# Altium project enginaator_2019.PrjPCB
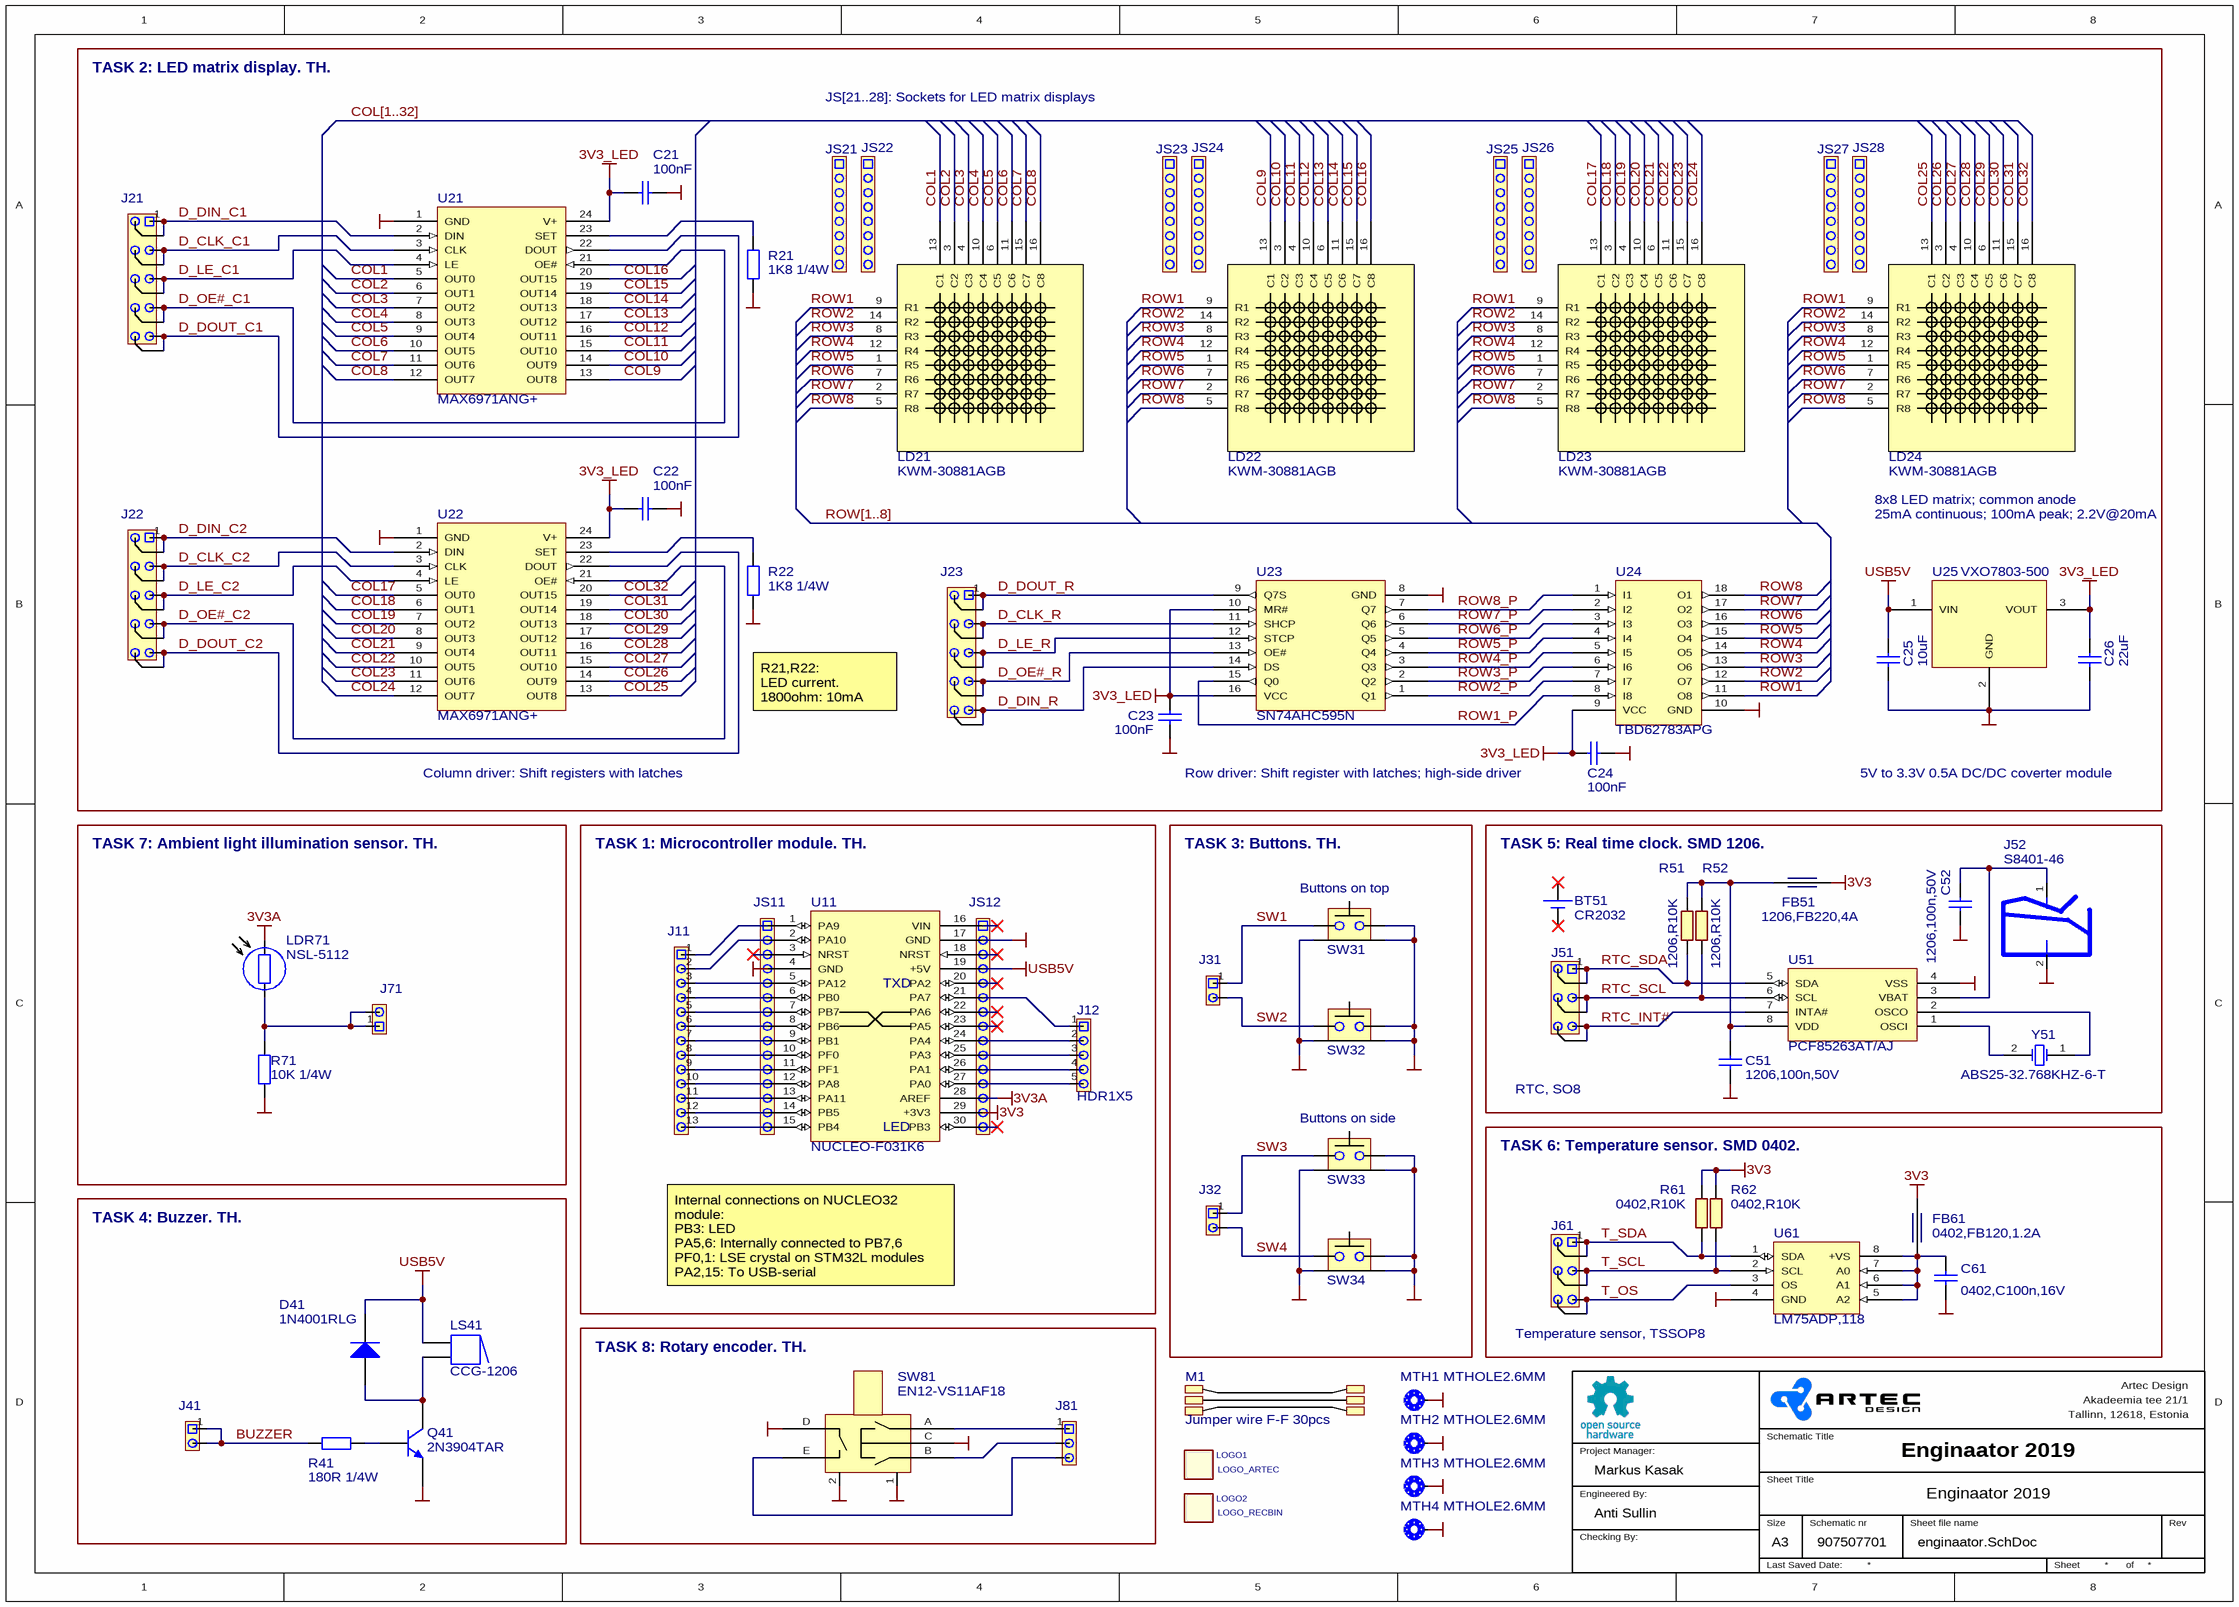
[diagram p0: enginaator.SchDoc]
ClientNr: 75; PCBDesigner: Anti Sullin; ProjectManager: Markus Kasak; ProjectNr: 077; ProjectTitle: Enginaator 2019; SchDesigner: Anti Sullin; Schematic_Title: Enginaator 2019; VersionNr: 01
1 sheet, 72 parts. Net scope: global (net labels, ports and power ports of the same name join across sheets).
Board file: enginaator.PcbDoc

## Sheet enginaator.SchDoc: Enginaator 2019
size A3; Size: A3

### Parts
BT51  CR2032  (mechanical)
C21  100nF  [CAP_TH_RADIAL_5MM]
C22  100nF  [CAP_TH_RADIAL_5MM]
C23  100nF  [CAP_TH_RADIAL_5MM]
C24  100nF  [CAP_TH_RADIAL_5MM]
C25  10uF  [CAP_TH_RADIAL_5MM]
C26  22uF  [CAP_TH_RADIAL_5MM]
C51  1206,100n,50V  [C1206]
C52  1206,100n,50V  [C1206]
C61  0402,C100n,16V  [C0402]
D41  1N4001RLG  [DIODE_TH_4x2MM]
FB51  1206,FB220,4A  [L1206]
FB61  0402,FB120,1.2A  [L0402]
J11  HDR1X13  [HDRTHV254P_1X13]  (value not drawn)
J12  HDR1X5  [HDRTHV254P_1X5]
J21  HDR2X5  [HDRTHv254P_2X5]  (value not drawn)
J22  HDR2X5  [hdrthv254p_2x5]  (value not drawn)
J23  HDR2X5  [hdrthv254p_2x5]  (value not drawn)
J31  HDR1X2  [HDRTHV254P_1X2]  (value not drawn)
J32  HDR1X2  [HDRTHV254P_1X2]  (value not drawn)
J41  HDR1X2  [HDRTHV254P_1X2]  (value not drawn)
J51  HDR2X3  [HDRTHV254P_2X3]  (value not drawn)
J52  S8401-46  [S8401-46]
J61  HDR2X3  [HDRTHV254P_2X3]  (value not drawn)
J71  HDR1X2  [HDRTHV254P_1X2]  (value not drawn)
J81  HDR1X3  [HDRTHV254P_1X3]  (value not drawn)
JS11  SOCKET_1X15  [HDRTHV254P_1X15_MECH]  (value not drawn)
JS12  SOCKET_1X15  [HDRTHV254P_1X15_MECH]  (value not drawn)
JS21  SOCKET_1X8  [HDRTHV254P_1X8_MECH]  (value not drawn)
JS22  SOCKET_1X8  [HDRTHV254P_1X8_MECH]  (value not drawn)
JS23  SOCKET_1X8  [HDRTHV254P_1X8_MECH]  (value not drawn)
JS24  SOCKET_1X8  [HDRTHV254P_1X8_MECH]  (value not drawn)
JS25  SOCKET_1X8  [HDRTHV254P_1X8_MECH]  (value not drawn)
JS26  SOCKET_1X8  [HDRTHV254P_1X8_MECH]  (value not drawn)
JS27  SOCKET_1X8  [HDRTHV254P_1X8_MECH]  (value not drawn)
JS28  SOCKET_1X8  [HDRTHV254P_1X8_MECH]  (value not drawn)
LD21  KWM-30881AGB  [LED8x8_32x32mm]
LD22  KWM-30881AGB  [LED8x8_32x32mm]
LD23  KWM-30881AGB  [LED8x8_32x32mm]
LD24  KWM-30881AGB  [LED8x8_32x32mm]
LDR71  NSL-5112  [PHOTODIODE_4MM]
LOGO1  LOGO_ARTEC  [LOGO_ARTEC]  (no BOM)
LOGO2  LOGO_RECBIN  [LOGO_RECBIN]  (no BOM)
LS41  CCG-1206  [BUZZER_12MM]
M1  Jumper wire F-F 30pcs  (mechanical)
MTH1  MTHOLE2.6MM  [MTHOLE2.6MM]  (no BOM)
MTH2  MTHOLE2.6MM  [MTHOLE2.6MM]  (no BOM)
MTH3  MTHOLE2.6MM  [MTHOLE2.6MM]  (no BOM)
MTH4  MTHOLE2.6MM  [MTHOLE2.6MM]  (no BOM)
Q41  2N3904TAR  [TO-226-AA-WIDE]
R21  1K8 1/4W  [AXIAL-0.4]
R22  1K8 1/4W  [AXIAL-0.4]
R41  180R 1/4W  [AXIAL-0.4]
R51  1206,R10K  [R1206]
R52  1206,R10K  [R1206]
R61  0402,R10K  [R0402]
R62  0402,R10K  [R0402]
R71  10K 1/4W  [AXIAL-0.4]
SW31  EVQ-PF106K  [SW_6x6_RA]  (value not drawn)
SW32  EVQ-PF106K  [SW_6x6_RA]  (value not drawn)
SW33  EVQ-PF106K  [SW_6x6_RA]  (value not drawn)
SW34  EVQ-PF106K  [SW_6x6_RA]  (value not drawn)
SW81  EN12-VS11AF18  [ROT_ENC_RA_12x12]
U11  NUCLEO-F031K6
U21  MAX6971ANG+  [DIP24-Narrow]
U22  MAX6971ANG+  [DIP24-Narrow]
U23  SN74AHC595N  [dip16]
U24  TBD62783APG
U25  VXO7803-500  [VXO7803-500]
U51  PCF85263AT/AJ  Properties: RTC, SO8  [SO8_HANDSOLDER]
U61  LM75ADP,118  Properties: Temperature sensor, TSSOP8  [SOT505-1_HANDSOLDER]
Y51  ABS25-32.768KHZ-6-T  [XTAL_8x3.8MM_HANDSOLDER]

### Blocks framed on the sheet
TASK 2: LED matrix display. TH.: C21-C26 J21-J23 JS21-JS28 LD21-LD24 R21 R22 U21-U25
TASK 7: Ambient light illumination sensor. TH.: J71 LDR71 R71
TASK 1: Microcontroller module. TH.: J11 J12 JS11 JS12 U11
TASK 3: Buttons. TH.: J31 J32 SW31-SW34
TASK 5: Real time clock. SMD 1206.: BT51 C51 C52 FB51 J51 J52 R51 R52 U51 Y51
TASK 6: Temperature sensor. SMD 0402.: C61 FB61 J61 R61 R62 U61
TASK 4: Buzzer. TH.: D41 J41 LS41 Q41 R41
TASK 8: Rotary encoder. TH.: J81 SW81

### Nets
3V3: FB51.1 FB61.2 R61.2 R62.2 U11.29(+3V3)
3V3_LED: C21.2 C22.2 C23.2 C24.2 C26.1 U21.24(V+) U22.24(V+) U23.10(MR#) U23.16(VCC) U24.9(VCC) U25.3(VOUT)
3V3A: LDR71.2 U11.28(AREF)
GND: C21.1 C22.1 C23.1 C24.1 C25.2 C26.2 C51.2 C52.2 C61.2 J52.2 MTH1.1 MTH2.1 MTH3.1 MTH4.1 Q41.3(E) R21.2 R22.2 R71.1 SW31.1 SW31.2 SW31.A SW32.1 SW32.2 SW32.B SW33.1 SW33.2 SW33.A SW34.1 SW34.2 SW34.B SW81.1 SW81.2 SW81.C SW81.D U11.4(GND) U11.17(GND) U21.1(GND) U22.1(GND) U23.8(GND) U24.10(GND) U25.2(GND) U51.4(VSS) U61.4(GND)
USB5V: C25.1 D41.2(K) LS41.1 U11.19(+5V) U25.1(VIN)
BUZZER: J41.1 J41.2 R41.1
COL1: LD21.13(C1) U21.5(OUT0)
COL2: LD21.3(C2) U21.6(OUT1)
COL3: LD21.4(C3) U21.7(OUT2)
COL4: LD21.10(C4) U21.8(OUT3)
COL5: LD21.6(C5) U21.9(OUT4)
COL6: LD21.11(C6) U21.10(OUT5)
COL7: LD21.15(C7) U21.11(OUT6)
COL8: LD21.16(C8) U21.12(OUT7)
COL9: LD22.13(C1) U21.13(OUT8)
COL10: LD22.3(C2) U21.14(OUT9)
COL11: LD22.4(C3) U21.15(OUT10)
COL12: LD22.10(C4) U21.16(OUT11)
COL13: LD22.6(C5) U21.17(OUT12)
COL14: LD22.11(C6) U21.18(OUT13)
COL15: LD22.15(C7) U21.19(OUT14)
COL16: LD22.16(C8) U21.20(OUT15)
COL17: LD23.13(C1) U22.5(OUT0)
COL18: LD23.3(C2) U22.6(OUT1)
COL19: LD23.4(C3) U22.7(OUT2)
COL20: LD23.10(C4) U22.8(OUT3)
COL21: LD23.6(C5) U22.9(OUT4)
COL22: LD23.11(C6) U22.10(OUT5)
COL23: LD23.15(C7) U22.11(OUT6)
COL24: LD23.16(C8) U22.12(OUT7)
COL25: LD24.13(C1) U22.13(OUT8)
COL26: LD24.3(C2) U22.14(OUT9)
COL27: LD24.4(C3) U22.15(OUT10)
COL28: LD24.10(C4) U22.16(OUT11)
COL29: LD24.6(C5) U22.17(OUT12)
COL30: LD24.11(C6) U22.18(OUT13)
COL31: LD24.15(C7) U22.19(OUT14)
COL32: LD24.16(C8) U22.20(OUT15)
D_CLK_C1: J21.3 J21.4 U21.3(CLK)
D_CLK_C2: J22.3 J22.4 U22.3(CLK)
D_CLK_R: J23.3 J23.4 U23.11(SHCP)
D_DIN_C1: J21.1 J21.2 U21.2(DIN)
D_DIN_C2: J22.1 J22.2 U22.2(DIN)
D_DIN_R: J23.9 J23.10 U23.14(DS)
D_DOUT_C1: J21.9 J21.10 U21.22(DOUT)
D_DOUT_C2: J22.9 J22.10 U22.22(DOUT)
D_DOUT_R: J23.1 J23.2 U23.9(Q7S)
D_LE_C1: J21.5 J21.6 U21.4(LE)
D_LE_C2: J22.5 J22.6 U22.4(LE)
D_LE_R: J23.5 J23.6 U23.12(STCP)
D_OE#_C1: J21.7 J21.8 U21.21(OE#)
D_OE#_C2: J22.7 J22.8 U22.21(OE#)
D_OE#_R: J23.7 J23.8 U23.13(OE#)
ROW1: LD21.9(R1) LD22.9(R1) LD23.9(R1) LD24.9(R1) U24.11(O8)
ROW1_P: U23.15(Q0) U24.8(I8)
ROW2: LD21.14(R2) LD22.14(R2) LD23.14(R2) LD24.14(R2) U24.12(O7)
ROW2_P: U23.1(Q1) U24.7(I7)
ROW3: LD21.8(R3) LD22.8(R3) LD23.8(R3) LD24.8(R3) U24.13(O6)
ROW3_P: U23.2(Q2) U24.6(I6)
ROW4: LD21.12(R4) LD22.12(R4) LD23.12(R4) LD24.12(R4) U24.14(O5)
ROW4_P: U23.3(Q3) U24.5(I5)
ROW5: LD21.1(R5) LD22.1(R5) LD23.1(R5) LD24.1(R5) U24.15(O4)
ROW5_P: U23.4(Q4) U24.4(I4)
ROW6: LD21.7(R6) LD22.7(R6) LD23.7(R6) LD24.7(R6) U24.16(O3)
ROW6_P: U23.5(Q5) U24.3(I3)
ROW7: LD21.2(R7) LD22.2(R7) LD23.2(R7) LD24.2(R7) U24.17(O2)
ROW7_P: U23.6(Q6) U24.2(I2)
ROW8: LD21.5(R8) LD22.5(R8) LD23.5(R8) LD24.5(R8) U24.18(O1)
ROW8_P: U23.7(Q7) U24.1(I1)
RTC_INT#: J51.5 J51.6 U51.7(INTA#)
RTC_SCL: J51.3 J51.4 R52.1 U51.6(SCL)
RTC_SDA: J51.1 J51.2 R51.1 U51.5(SDA)
SW1: J31.1 SW31.B
SW2: J31.2 SW32.A
SW3: J32.1 SW33.B
SW4: J32.2 SW34.A
T_OS: J61.5 J61.6 U61.3(OS)
T_SCL: J61.3 J61.4 R62.1 U61.2(SCL)
T_SDA: J61.1 J61.2 R61.1 U61.1(SDA)
NetC51_1: C51.1 FB51.2 R51.2 R52.2 U51.8(VDD)
NetC52_1: C52.1 J52.1 U51.3(VBAT)
NetC61_1: C61.1 FB61.1 U61.5(A2) U61.6(A1) U61.7(A0) U61.8(+VS)
NetD41_1: D41.1(A) LS41.2 Q41.1(C)
NetJ11_1: J11.1 U11.1(PA9)
NetJ11_2: J11.2 U11.2(PA10)
NetJ11_3: J11.3 U11.5(PA12)
NetJ11_4: J11.4 U11.6(PB0)
NetJ11_5: J11.5 U11.7(PB7)
NetJ11_6: J11.6 U11.8(PB6)
NetJ11_7: J11.7 U11.9(PB1)
NetJ11_8: J11.8 U11.10(PF0)
NetJ11_9: J11.9 U11.11(PF1)
NetJ11_10: J11.10 U11.12(PA8)
NetJ11_11: J11.11 U11.13(PA11)
NetJ11_12: J11.12 U11.14(PB5)
NetJ11_13: J11.13 U11.15(PB4)
NetJ12_1: J12.1 U11.21(PA7)
NetJ12_2: J12.2 U11.24(PA4)
NetJ12_3: J12.3 U11.25(PA3)
NetJ12_4: J12.4 U11.26(PA1)
NetJ12_5: J12.5 U11.27(PA0)
NetJ71_1: J71.1 J71.2 LDR71.1 R71.2
NetJ81_1: J81.1 SW81.A
NetJ81_2: J81.2 SW81.B
NetJ81_3: J81.3 SW81.E
NetQ41_2: Q41.2(B) R41.2
NetR21_1: R21.1 U21.23(SET)
NetR22_1: R22.1 U22.23(SET)
NetU51_1: U51.1(OSCI) Y51.2(OSC2)
NetU51_2: U51.2(OSCO) Y51.1(OSC1)

Not connected (* = marked no-connect by the designer): BT51 1(+)* 2(-)*; U11 3(NRST)* 16(VIN)* 18(NRST)* 20(PA2)* 22(PA6)* 23(PA5)* 30(PB3)*

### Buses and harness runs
bus COL[1..32]
bus ROW[1..8]

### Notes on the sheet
- JS[21..28]: Sockets for LED matrix displays
- 8x8 LED matrix; common anode
- 25mA continuous; 100mA peak; 2.2V@20mA
- R21,R22:
  LED current.
  1800ohm: 10mA
- Column driver: Shift registers with latches
- Row driver: Shift register with latches; high-side driver
- 5V to 3.3V 0.5A DC/DC coverter module
- (near SW31) Buttons on top
- (near U11) TXD
- (near U11) LED
- (near SW33) Buttons on side
- Internal connections on NUCLEO32 module:
  PB3: LED
  PA5,6: Internally connected to PB7,6
  PF0,1: LSE crystal on STM32L modules
  PA2,15: To USB-serial
  PA13,14: To SWD debug interface
- Artec Design
- Akadeemia tee 21/1
- Project Manager:
- Sheet Title
- Schematic Title
- Tallinn, 12618, Estonia
- Engineered By:
- Checking By:
- Size
- Schematic nr
- Sheet file name
- Rev
- Last Saved Date:
- Sheet
- of

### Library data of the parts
BT51 = BAT
C21-C24 = CAP_RADIAL_5MM: CAP 0.1UF 10% 63VDC RADIAL 5.0mm; Manufacturer: AVX Corporation; Value: 100nF,radial,5mm
C25 = CAP_RADIAL_5MM: Manufacturer: TDK Corporation; Value: 10uF,radial,5mm
C26 = CAP_RADIAL_5MM: Manufacturer: TDK Corporation; Value: 22uF,radial,5mm
C51 C52 = 1206,100n,50V: 1206, C100n, 50V, +/-10%; Manufacturer: Yageo; ADGPN: 2021210400; Properties: 50V +/-10%
C61 = 0402,C100n,16V: 0402, C100n, 16V, +/-10%, X7R; Manufacturer: Murata; ADGPN: R2001040600; Properties: 16V, +/10%, X7R
D41 = Diode: Default Diode; Manufacturer: ON Semiconductor
FB51 = 1206,FB220,4A: 1206, FB220, 4A, 20mOhm, FBMH3216HM221NT; Manufacturer: Taiyo Yuden; ADGPN: 4901022010; Properties: 220Ohm, DC 20mOhm
FB61 = 0402,FB120,1.2A: 0402, FB120,1200mA; Manufacturer: TDK; ADGPN: 4901012020; Properties: Ferr Chip Beads 120 Om 1200mA
J11 = HDR1X13: Manufacturer: CONNFLY
J21 = HDR2X5: Manufacturer: CONNFLY
J52 = S8401-46: S8401-46 Battery Holder, Vertical, H=16.9mm,  20mm coin, CR2032, -40+105C, TH, Harwin; ADGPN: 4220034600
JS11 JS12 = HDR1X15_MECH: Manufacturer: NINIGI
JS21-JS28 = HDR1X8_MECH: Manufacturer: CONNFLY
LD21-LD24 = LED_MATRIX_8x8: Manufacturer: LUCKY LIGHT
LDR71 = PHOTORES: Manufacturer: Advanced Photonix
LOGO1 LOGO2 = BOM_only
LS41 = Buzzer: Magnetic Transducer Buzzer; Manufacturer: CUI Inc.
M1 = JUMPERWIRE: Manufacturer: Adafruit Industries LLC
MTH1-MTH4 = MTHOLE2.6MM: MTHOLE2.6MM, M2.5 Mounting hole 2.9mm, plated; Manufacturer: NA; ADGPN: 2699002600; Properties: Mounting hole 2.6mm, M2.5, tight fit, plated
Q41 = NPN: NPN Bipolar Transistor; Manufacturer: ON Semi
R21 R22 R71 = Res2: RES 1.8K OHM 1/4W 5% AXIAL; Manufacturer: Yageo
R41 = Res2: Resistor; Manufacturer: Yageo
R51 R52 = 1206,R10K: 1206, R10K, 1/4W, 1%; Manufacturer: Yageo; ADGPN: 7526100240
R61 R62 = 0402,R10K: 0402, R10K, 1/16W, 1%, RC0402FR-0710KL, Yageo; ADGPN: 7542100200; Properties: 1%,1/16W, 50V
SW31-SW34 = SW_TACTILE: Manufacturer: Panasonic Electronic Components
SW81 = ROT_ENC_SW: Manufacturer: TT Electronics/BI
U11 = NUCLEO32: Manufacturer: STMicroelectronics
U21 U22 = MAX6971: Manufacturer: Maxim
U23 = 74HCT595: Manufacturer: TI
U24 = TBD62xxx: Manufacturer: Toshiba Semiconductor and Storage
U25 = VXO78-500: Manufacturer: CUI Inc.
U51 = PCF85263AT: Manufacturer: NXP
U61 = LM75A: SENSOR DIGITAL -55C-125C 8TSSOP; Manufacturer: NXP
Y51 = XTAL: Crystal Oscillator; Manufacturer: Abracon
